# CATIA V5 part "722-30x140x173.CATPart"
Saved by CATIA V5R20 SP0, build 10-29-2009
Part number: 722-30x140x173
Definition: NONE
Nomenclature: 722-30x140x173
Source: Unknown
Description: 722-30x140x173
Bounding box of the stored display mesh (mm): x -15 to 15, y -15 to 15, z -125 to 48
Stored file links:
  C:\Users\Utente\Desktop\IO LAVORO\3D X SITO CF\X SITO\722\722-30x140x173.CATPart
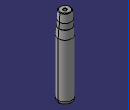
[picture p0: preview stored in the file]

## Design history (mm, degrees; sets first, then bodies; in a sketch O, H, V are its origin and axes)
Body1 "722-30x140x173" (main body)
  Solid1: solid without history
